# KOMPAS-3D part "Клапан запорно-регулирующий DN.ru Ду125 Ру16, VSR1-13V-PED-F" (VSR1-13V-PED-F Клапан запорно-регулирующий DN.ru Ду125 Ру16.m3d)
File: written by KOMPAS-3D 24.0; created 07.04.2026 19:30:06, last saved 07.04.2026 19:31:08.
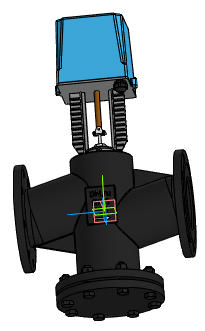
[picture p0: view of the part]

Document properties: Автор: R2D2; Полное имя файла: E:\Работа\Зайцев\Солянка\VSR1-13V-PED-F Клапан запорно-регулирующий DN.ru\DN125\VSR1-13V-PED-F Клапан запорно-регулирующий DN.ru Ду125 Ру16.m3d

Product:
- Part/product: Клапан запорно-регулирующий DN.ru Ду125 Ру16  | designation VSR1-13V-PED-F
    Масса: 40.6
    Раздел спецификации: Прочие изделия
    Примечание: D090-02895

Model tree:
1. Операция без истории:1  (labels: SHAPEOBJECT3D_ATTR_BUTT)

Expressions: VSR1-13V-PED-F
